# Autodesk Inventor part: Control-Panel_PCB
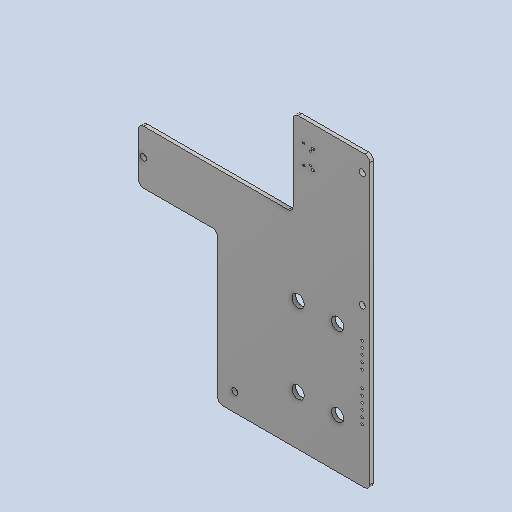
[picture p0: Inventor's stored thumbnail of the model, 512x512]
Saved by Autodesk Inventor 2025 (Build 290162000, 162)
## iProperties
Created: 2026-09
Part Number: Control-Panel_PCB
Material: Generic
Document SubType Name: Modeling
Designer: Leonardo
Density: 1 g/cm^3
Appearance: Default
Author: Leonardo
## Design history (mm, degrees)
feature "Base1"
body "Solid1"
